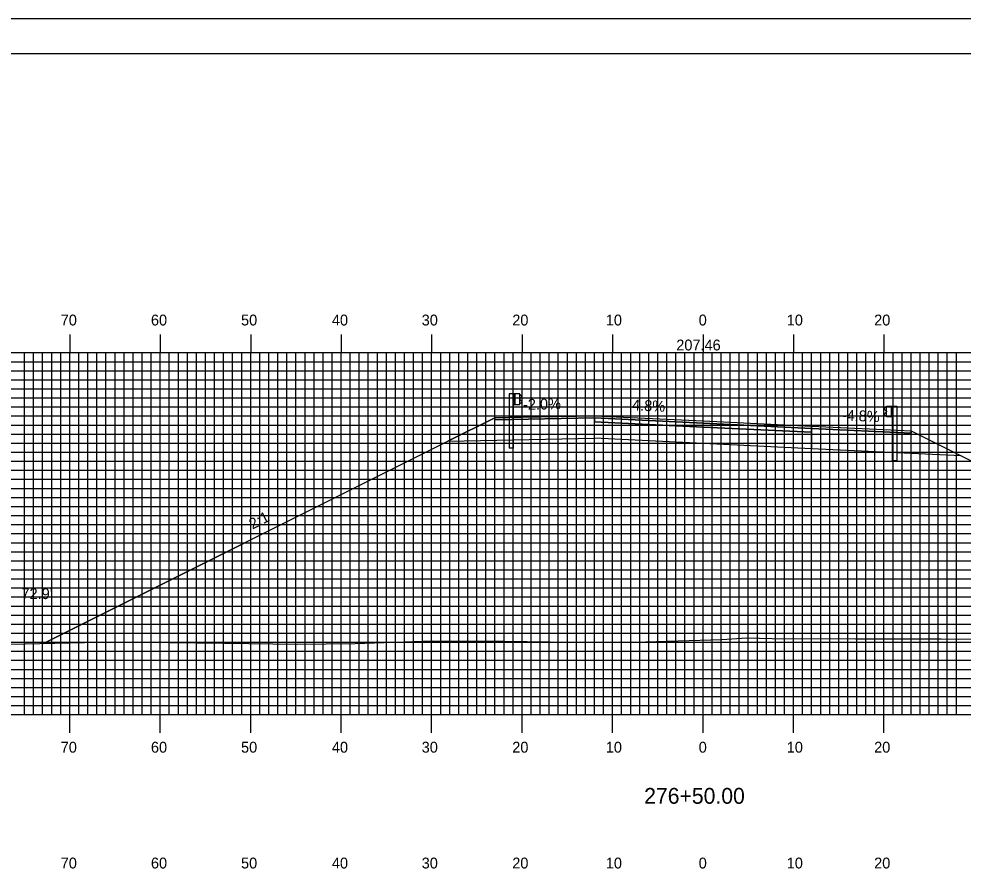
# Model space of a CAD drawing. Extents: x 1809800 to 1810143, y 442591 to 442811.
# Drawn here: x 1809889.7 to 1809994.1, y 442716.2 to 442810.5 of the extents above; entities that cross this region are included whole.
import ezdxf

# ---------------------------------------------------------------- set-up
doc = ezdxf.new("R2010")
doc.units = 0
for name, color, linetype in [('ANNOTATION', 7, 'Continuous'), ('BORDER', 7, 'Continuous'), ('D_Guardrail_Beam_Lt', 7, 'Continuous'), ('D_Guardrail_Beam_Rt', 7, 'Continuous'), ('D_Roadway_Centerline', 7, 'Continuous'), ('D_Roadway_Centerline_Text', 7, 'Continuous'), ('D_Roadway_Edge_Shoulder', 7, 'Continuous'), ('D_Roadway_Edge_TW', 7, 'Continuous'), ('D_Roadway_Pavement', 7, 'Continuous'), ('D_Roadway_SlopeLines', 7, 'Continuous'), ('D_Roadway_SubGrade', 7, 'Continuous'), ('D_Text_Standard', 7, 'Continuous'), ('H_V ANNOTATION', 7, 'Continuous'), ('MAJOR', 7, 'Continuous'), ('MINOR', 7, 'Continuous'), ('PLOT BOUNDARY', 7, 'Continuous'), ('S_Roadway_Centerline', 7, 'Continuous')]:
    doc.layers.add(name, color=color, linetype=linetype)

msp = doc.modelspace()

# ---------------------------------------------------------------- linework, layer by layer
at = {"layer": 'BORDER'}
msp.add_lwpolyline([(1809815.75, 442596.67), (1810135.75, 442596.67), (1810135.75, 442806.67), (1809815.75, 442806.67)], close=True, dxfattribs=at)
at = {"layer": 'D_Guardrail_Beam_Lt'}
for p, q in [((1809943.92, 442769.12), (1809943.92, 442763.12)), ((1809944.39, 442769.12), (1809943.92, 442769.12)), ((1809945.08, 442769.12), (1809944.39, 442769.12)), ((1809944.39, 442769.12), (1809944.39, 442767.95)), ((1809944.45, 442769.12), (1809944.45, 442767.95)), ((1809944.56, 442769.12), (1809944.56, 442767.95)), ((1809945.08, 442767.95), (1809945.08, 442769.12)), ((1809945.08, 442769.04), (1809945.15, 442769.02)), ((1809945.31, 442768.77), (1809945.12, 442768.64)), ((1809945.17, 442769.01), (1809945.31, 442768.91)), ((1809944.39, 442767.95), (1809945.08, 442767.95)), ((1809944.41, 442763.12), (1809944.41, 442767.95)), ((1809945.08, 442768.57), (1809945.08, 442768.5)), ((1809945.15, 442768.05), (1809945.08, 442768.04)), ((1809945.12, 442768.44), (1809945.31, 442768.3)), ((1809945.31, 442768.16), (1809945.17, 442768.06)), ((1809944.41, 442763.12), (1809943.92, 442763.12))]:
    msp.add_line(p, q, dxfattribs=at)
for centre, major_axis, start_param, end_param in [((1809945.16, 442768.57), (-0.0789, 0), 5.323254, 6.283185), ((1809945.15, 442768.98), (0.0417, 0), 0.959931, 1.376053), ((1809945.26, 442768.84), (0.0877, 0), 5.323254, 7.243116), ((1809945.16, 442768.5), (-0.0789, 0), 6.283185, 7.243116), ((1809945.15, 442768.09), (0.0417, 0), 4.907132, 5.323254), ((1809945.26, 442768.23), (0.0877, 0), 5.323254, 7.243116)]:
    msp.add_ellipse(centre, major_axis=major_axis, ratio=0.995501, start_param=start_param, end_param=end_param, dxfattribs=at)
at = {"layer": 'D_Guardrail_Beam_Rt'}
for p, q in [((1809985.53, 442767.64), (1809985.39, 442767.54)), ((1809985.62, 442767.66), (1809985.55, 442767.65)), ((1809985.62, 442767.74), (1809986.31, 442767.74)), ((1809985.62, 442766.58), (1809985.62, 442767.74)), ((1809986.14, 442767.74), (1809986.14, 442766.58)), ((1809986.25, 442767.74), (1809986.25, 442766.58)), ((1809986.31, 442767.74), (1809986.78, 442767.74)), ((1809986.31, 442767.74), (1809986.31, 442766.58)), ((1809986.78, 442767.74), (1809986.78, 442761.74)), ((1809985.39, 442767.4), (1809985.58, 442767.26)), ((1809985.58, 442767.06), (1809985.39, 442766.92)), ((1809985.39, 442766.78), (1809985.53, 442766.68)), ((1809985.55, 442766.67), (1809985.62, 442766.66)), ((1809985.62, 442767.2), (1809985.62, 442767.13)), ((1809986.31, 442766.58), (1809985.62, 442766.58)), ((1809986.29, 442761.74), (1809986.29, 442766.58)), ((1809986.29, 442761.74), (1809986.78, 442761.74))]:
    msp.add_line(p, q, dxfattribs=at)
for centre, major_axis, start_param, end_param in [((1809985.56, 442767.6), (-0.0417, 0), 4.907132, 5.323254), ((1809985.44, 442767.47), (-0.0877, 0), 5.323254, 7.243116), ((1809985.44, 442766.85), (-0.0877, 0), 5.323254, 7.243116), ((1809985.56, 442766.72), (-0.0417, 0), 0.959931, 1.376053), ((1809985.54, 442767.2), (0.0789, 0), 0, 0.959931), ((1809985.54, 442767.13), (0.0789, 0), 5.323254, 6.283185)]:
    msp.add_ellipse(centre, major_axis=major_axis, ratio=0.995501, start_param=start_param, end_param=end_param, dxfattribs=at)
at = {"layer": 'D_Roadway_Centerline'}
msp.add_lwpolyline([(1809892.44, 442741.52), (1809937.14, 442763.87), (1809942.35, 442766.48), (1809945.35, 442766.54), (1809953.35, 442766.7), (1809965.35, 442766.12), (1809977.35, 442765.54), (1809985.35, 442765.16), (1809988.35, 442765.02), (1809993.88, 442762.25), (1810034.75, 442741.82)], dxfattribs=at)
at = {"layer": 'D_Roadway_Edge_Shoulder'}
for points in [[(1809953.35, 442766.7), (1809945.35, 442766.54), (1809945.35, 442766.54), (1809942.35, 442766.48), (1809942.35, 442766.23), (1809953.35, 442766.45)], [(1809977.35, 442765.54), (1809985.35, 442765.16), (1809985.35, 442765.16), (1809988.35, 442765.02), (1809988.35, 442764.77), (1809977.35, 442765.29)]]:
    msp.add_lwpolyline(points, close=True, dxfattribs=at)
at = {"layer": 'D_Roadway_Edge_TW'}
msp.add_lwpolyline([(1809953.35, 442766.45), (1809953.35, 442766.7), (1809965.35, 442766.12), (1809977.35, 442765.54), (1809977.35, 442765.29), (1809965.35, 442765.87)], close=True, dxfattribs=at)
at = {"layer": 'D_Roadway_Pavement'}
msp.add_lwpolyline([(1809953.35, 442766.03), (1809953.35, 442766.45), (1809965.35, 442765.87), (1809977.35, 442765.29), (1809977.35, 442764.88), (1809965.35, 442765.45)], close=True, dxfattribs=at)
for points in [[(1809953.35, 442766.45), (1809953.35, 442766.03)], [(1809977.35, 442765.29), (1809977.35, 442764.88)]]:
    msp.add_lwpolyline(points, dxfattribs=at)
at = {"layer": 'D_Roadway_SlopeLines'}
for points in [[(1809942.35, 442766.48), (1809892.44, 442741.52)], [(1809988.35, 442765.02), (1810034.75, 442741.82)]]:
    msp.add_lwpolyline(points, dxfattribs=at)
at = {"layer": 'D_Roadway_SubGrade'}
for points in [[(1809953.35, 442766.03), (1809953.35, 442766.45), (1809942.35, 442766.23), (1809942.35, 442766.48), (1809937.14, 442763.87), (1809953.35, 442764.2)], [(1809953.35, 442764.2), (1809953.35, 442766.45), (1809953.35, 442766.03), (1809965.35, 442765.45), (1809977.35, 442764.88), (1809977.35, 442765.29), (1809977.35, 442763.04), (1809965.35, 442763.62)], [(1809977.35, 442764.88), (1809977.35, 442765.29), (1809988.35, 442764.77), (1809988.35, 442765.02), (1809993.88, 442762.25), (1809977.35, 442763.04)]]:
    msp.add_lwpolyline(points, close=True, dxfattribs=at)
at = {"layer": 'MAJOR'}
for p, q in [((1809895.35, 442775.67), (1809895.35, 442773.67)), ((1809905.35, 442775.67), (1809905.35, 442773.67)), ((1809915.35, 442775.67), (1809915.35, 442773.67)), ((1809925.35, 442775.67), (1809925.35, 442773.67)), ((1809935.35, 442775.67), (1809935.35, 442773.67)), ((1809945.35, 442775.67), (1809945.35, 442773.67)), ((1809955.35, 442775.67), (1809955.35, 442773.67)), ((1809965.35, 442775.67), (1809965.35, 442773.67)), ((1809975.35, 442775.67), (1809975.35, 442773.67)), ((1809985.35, 442775.67), (1809985.35, 442773.67)), ((1809825.35, 442773.67), (1810105.35, 442773.67)), ((1809825.35, 442773.67), (1810105.35, 442773.67)), ((1809895.35, 442733.67), (1809895.35, 442773.67)), ((1809905.35, 442733.67), (1809905.35, 442773.67)), ((1809915.35, 442733.67), (1809915.35, 442773.67)), ((1809925.35, 442733.67), (1809925.35, 442773.67)), ((1809935.35, 442733.67), (1809935.35, 442773.67)), ((1809945.35, 442733.67), (1809945.35, 442773.67)), ((1809955.35, 442733.67), (1809955.35, 442773.67)), ((1809965.35, 442733.67), (1809965.35, 442773.67)), ((1809975.35, 442733.67), (1809975.35, 442773.67)), ((1809985.35, 442733.67), (1809985.35, 442773.67)), ((1809825.35, 442768.67), (1810105.35, 442768.67)), ((1809825.35, 442763.67), (1810105.35, 442763.67)), ((1809825.35, 442758.67), (1810105.35, 442758.67)), ((1809825.35, 442753.67), (1810105.35, 442753.67)), ((1809825.35, 442748.67), (1810105.35, 442748.67)), ((1809825.35, 442743.67), (1810105.35, 442743.67)), ((1809825.35, 442738.67), (1810105.35, 442738.67)), ((1809825.35, 442733.67), (1810105.35, 442733.67)), ((1809825.35, 442733.67), (1810105.35, 442733.67)), ((1809895.35, 442731.66), (1809895.35, 442733.67)), ((1809905.35, 442731.66), (1809905.35, 442733.67)), ((1809915.35, 442731.66), (1809915.35, 442733.67)), ((1809925.35, 442731.66), (1809925.35, 442733.67)), ((1809935.35, 442731.66), (1809935.35, 442733.67)), ((1809945.35, 442731.66), (1809945.35, 442733.67)), ((1809955.35, 442731.66), (1809955.35, 442733.67)), ((1809965.35, 442731.66), (1809965.35, 442733.67)), ((1809975.35, 442731.66), (1809975.35, 442733.67)), ((1809985.35, 442731.66), (1809985.35, 442733.67))]:
    msp.add_line(p, q, dxfattribs=at)
at = {"layer": 'MINOR'}
for p, q in [((1809890.35, 442733.67), (1809890.35, 442773.67)), ((1809891.35, 442733.67), (1809891.35, 442773.67)), ((1809892.35, 442733.67), (1809892.35, 442773.67)), ((1809893.35, 442733.67), (1809893.35, 442773.67)), ((1809894.35, 442733.67), (1809894.35, 442773.67)), ((1809896.35, 442733.67), (1809896.35, 442773.67)), ((1809897.35, 442733.67), (1809897.35, 442773.67)), ((1809898.35, 442733.67), (1809898.35, 442773.67)), ((1809899.35, 442733.67), (1809899.35, 442773.67)), ((1809900.35, 442733.67), (1809900.35, 442773.67)), ((1809901.35, 442733.67), (1809901.35, 442773.67)), ((1809902.35, 442733.67), (1809902.35, 442773.67)), ((1809903.35, 442733.67), (1809903.35, 442773.67)), ((1809904.35, 442733.67), (1809904.35, 442773.67)), ((1809906.35, 442733.67), (1809906.35, 442773.67)), ((1809907.35, 442733.67), (1809907.35, 442773.67)), ((1809908.35, 442733.67), (1809908.35, 442773.67)), ((1809909.35, 442733.67), (1809909.35, 442773.67)), ((1809910.35, 442733.67), (1809910.35, 442773.67)), ((1809911.35, 442733.67), (1809911.35, 442773.67)), ((1809912.35, 442733.67), (1809912.35, 442773.67)), ((1809913.35, 442733.67), (1809913.35, 442773.67)), ((1809914.35, 442733.67), (1809914.35, 442773.67)), ((1809916.35, 442733.67), (1809916.35, 442773.67)), ((1809917.35, 442733.67), (1809917.35, 442773.67)), ((1809918.35, 442733.67), (1809918.35, 442773.67)), ((1809919.35, 442733.67), (1809919.35, 442773.67)), ((1809920.35, 442733.67), (1809920.35, 442773.67)), ((1809921.35, 442733.67), (1809921.35, 442773.67)), ((1809922.35, 442733.67), (1809922.35, 442773.67)), ((1809923.35, 442733.67), (1809923.35, 442773.67)), ((1809924.35, 442733.67), (1809924.35, 442773.67)), ((1809926.35, 442733.67), (1809926.35, 442773.67)), ((1809927.35, 442733.67), (1809927.35, 442773.67)), ((1809928.35, 442733.67), (1809928.35, 442773.67)), ((1809929.35, 442733.67), (1809929.35, 442773.67)), ((1809930.35, 442733.67), (1809930.35, 442773.67)), ((1809931.35, 442733.67), (1809931.35, 442773.67)), ((1809932.35, 442733.67), (1809932.35, 442773.67)), ((1809933.35, 442733.67), (1809933.35, 442773.67)), ((1809934.35, 442733.67), (1809934.35, 442773.67)), ((1809936.35, 442733.67), (1809936.35, 442773.67)), ((1809937.35, 442733.67), (1809937.35, 442773.67)), ((1809938.35, 442733.67), (1809938.35, 442773.67)), ((1809939.35, 442733.67), (1809939.35, 442773.67)), ((1809940.35, 442733.67), (1809940.35, 442773.67)), ((1809941.35, 442733.67), (1809941.35, 442773.67)), ((1809942.35, 442733.67), (1809942.35, 442773.67)), ((1809943.35, 442733.67), (1809943.35, 442773.67)), ((1809944.35, 442733.67), (1809944.35, 442773.67)), ((1809946.35, 442733.67), (1809946.35, 442773.67)), ((1809947.35, 442733.67), (1809947.35, 442773.67)), ((1809948.35, 442733.67), (1809948.35, 442773.67)), ((1809949.35, 442733.67), (1809949.35, 442773.67)), ((1809950.35, 442733.67), (1809950.35, 442773.67)), ((1809951.35, 442733.67), (1809951.35, 442773.67)), ((1809952.35, 442733.67), (1809952.35, 442773.67)), ((1809953.35, 442733.67), (1809953.35, 442773.67)), ((1809954.35, 442733.67), (1809954.35, 442773.67)), ((1809956.35, 442733.67), (1809956.35, 442773.67)), ((1809957.35, 442733.67), (1809957.35, 442773.67)), ((1809958.35, 442733.67), (1809958.35, 442773.67)), ((1809959.35, 442733.67), (1809959.35, 442773.67)), ((1809960.35, 442733.67), (1809960.35, 442773.67)), ((1809961.35, 442733.67), (1809961.35, 442773.67)), ((1809962.35, 442733.67), (1809962.35, 442773.67)), ((1809963.35, 442733.67), (1809963.35, 442773.67)), ((1809964.35, 442733.67), (1809964.35, 442773.67)), ((1809966.35, 442733.67), (1809966.35, 442773.67)), ((1809967.35, 442733.67), (1809967.35, 442773.67)), ((1809968.35, 442733.67), (1809968.35, 442773.67)), ((1809969.35, 442733.67), (1809969.35, 442773.67)), ((1809970.35, 442733.67), (1809970.35, 442773.67)), ((1809971.35, 442733.67), (1809971.35, 442773.67)), ((1809972.35, 442733.67), (1809972.35, 442773.67)), ((1809973.35, 442733.67), (1809973.35, 442773.67)), ((1809974.35, 442733.67), (1809974.35, 442773.67)), ((1809976.35, 442733.67), (1809976.35, 442773.67)), ((1809977.35, 442733.67), (1809977.35, 442773.67)), ((1809978.35, 442733.67), (1809978.35, 442773.67)), ((1809979.35, 442733.67), (1809979.35, 442773.67)), ((1809980.35, 442733.67), (1809980.35, 442773.67)), ((1809981.35, 442733.67), (1809981.35, 442773.67)), ((1809982.35, 442733.67), (1809982.35, 442773.67)), ((1809983.35, 442733.67), (1809983.35, 442773.67)), ((1809984.35, 442733.67), (1809984.35, 442773.67)), ((1809986.35, 442733.67), (1809986.35, 442773.67)), ((1809987.35, 442733.67), (1809987.35, 442773.67)), ((1809988.35, 442733.67), (1809988.35, 442773.67)), ((1809989.35, 442733.67), (1809989.35, 442773.67)), ((1809990.35, 442733.67), (1809990.35, 442773.67)), ((1809991.35, 442733.67), (1809991.35, 442773.67)), ((1809992.35, 442733.67), (1809992.35, 442773.67)), ((1809993.35, 442733.67), (1809993.35, 442773.67)), ((1809825.35, 442772.67), (1810105.35, 442772.67)), ((1809825.35, 442771.67), (1810105.35, 442771.67)), ((1809825.35, 442770.67), (1810105.35, 442770.67)), ((1809825.35, 442769.67), (1810105.35, 442769.67)), ((1809825.35, 442767.67), (1810105.35, 442767.67)), ((1809825.35, 442766.67), (1810105.35, 442766.67)), ((1809825.35, 442765.67), (1810105.35, 442765.67)), ((1809825.35, 442764.67), (1810105.35, 442764.67)), ((1809825.35, 442762.67), (1810105.35, 442762.67)), ((1809825.35, 442761.67), (1810105.35, 442761.67)), ((1809825.35, 442760.67), (1810105.35, 442760.67)), ((1809825.35, 442759.67), (1810105.35, 442759.67)), ((1809825.35, 442757.67), (1810105.35, 442757.67)), ((1809825.35, 442756.67), (1810105.35, 442756.67)), ((1809825.35, 442755.67), (1810105.35, 442755.67)), ((1809825.35, 442754.67), (1810105.35, 442754.67)), ((1809825.35, 442752.67), (1810105.35, 442752.67)), ((1809825.35, 442751.67), (1810105.35, 442751.67)), ((1809825.35, 442750.67), (1810105.35, 442750.67)), ((1809825.35, 442749.67), (1810105.35, 442749.67)), ((1809825.35, 442747.67), (1810105.35, 442747.67)), ((1809825.35, 442746.67), (1810105.35, 442746.67)), ((1809825.35, 442745.67), (1810105.35, 442745.67)), ((1809825.35, 442744.67), (1810105.35, 442744.67)), ((1809825.35, 442742.67), (1810105.35, 442742.67)), ((1809825.35, 442741.67), (1810105.35, 442741.67)), ((1809825.35, 442740.67), (1810105.35, 442740.67)), ((1809825.35, 442739.67), (1810105.35, 442739.67)), ((1809825.35, 442737.67), (1810105.35, 442737.67)), ((1809825.35, 442736.67), (1810105.35, 442736.67)), ((1809825.35, 442735.67), (1810105.35, 442735.67)), ((1809825.35, 442734.67), (1810105.35, 442734.67))]:
    msp.add_line(p, q, dxfattribs=at)
at = {"layer": 'PLOT BOUNDARY'}
msp.add_lwpolyline([(1809799.56, 442590.55), (1810139.56, 442590.55), (1810139.56, 442810.55), (1809799.56, 442810.55)], close=True, dxfattribs=at)
at = {"layer": 'S_Roadway_Centerline'}
msp.add_lwpolyline([(1809877.29, 442741.19), (1809898.61, 442741.66), (1809900.89, 442741.66), (1809903.26, 442741.66), (1809912.44, 442741.58), (1809920.49, 442741.46), (1809926.9, 442741.53), (1809935.49, 442741.81), (1809943.39, 442741.79), (1809948.45, 442741.73), (1809957.76, 442741.67), (1809967.42, 442741.98), (1809970.2, 442742.14), (1809972.99, 442742.09), (1809982.19, 442742.06), (1809991.67, 442742.04), (1809993.6, 442742), (1809995.7, 442742.05)], dxfattribs=at)

# ---------------------------------------------------------------- texts
at = {"layer": 'ANNOTATION'}
for s, rotation, p in [('-2.0%', 1.1458, (1809945.46, 442767.34)), ('4.8%', 357.2519, (1809957.48, 442767.3)), ('-4.8%', 357.2519, (1809980.66, 442766.19)), ('2:1', 26.5651, (1809915.54, 442754.11))]:
    msp.add_text(s, height=1.2, rotation=rotation, dxfattribs=at).set_placement(p)
at = {"layer": 'D_Roadway_Centerline'}
for s, p in [('C', (1809965.35, 442766.12)), ('L', (1809965.35, 442766.11))]:
    msp.add_text(s, height=0.0146, dxfattribs=at).set_placement(p)
at = {"layer": 'D_Roadway_Centerline_Text'}
msp.add_text('207.46', height=1.2, dxfattribs=at).set_placement((1809962.39, 442773.91))
at = {"layer": 'D_Text_Standard'}
msp.add_text("72.9'", height=1.2, dxfattribs=at).set_placement((1809890.01, 442746.44))
at = {"layer": 'H_V ANNOTATION'}
for s, height, p in [('70', 1.2, (1809894.35, 442776.67)), ('60', 1.2, (1809904.32, 442776.67)), ('50', 1.2, (1809914.28, 442776.67)), ('40', 1.2, (1809924.32, 442776.67)), ('30', 1.2, (1809934.25, 442776.67)), ('20', 1.2, (1809944.26, 442776.67)), ('10', 1.2, (1809954.6, 442776.67)), ('0', 1.2, (1809964.87, 442776.67)), ('10', 1.2, (1809974.6, 442776.67)), ('20', 1.2, (1809984.26, 442776.67)), ('70', 1.2, (1809894.35, 442729.47)), ('60', 1.2, (1809904.32, 442729.47)), ('50', 1.2, (1809914.28, 442729.47)), ('40', 1.2, (1809924.32, 442729.47)), ('30', 1.2, (1809934.25, 442729.47)), ('20', 1.2, (1809944.26, 442729.47)), ('10', 1.2, (1809954.6, 442729.47)), ('0', 1.2, (1809964.87, 442729.47)), ('10', 1.2, (1809974.6, 442729.47)), ('20', 1.2, (1809984.26, 442729.47)), ('276+50.00', 1.75, (1809958.84, 442723.82)), ('70', 1.2, (1809894.35, 442716.67)), ('60', 1.2, (1809904.32, 442716.67)), ('50', 1.2, (1809914.28, 442716.67)), ('40', 1.2, (1809924.32, 442716.67)), ('30', 1.2, (1809934.25, 442716.67)), ('20', 1.2, (1809944.26, 442716.67)), ('10', 1.2, (1809954.6, 442716.67)), ('0', 1.2, (1809964.87, 442716.67)), ('10', 1.2, (1809974.6, 442716.67)), ('20', 1.2, (1809984.26, 442716.67))]:
    msp.add_text(s, height=height, dxfattribs=at).set_placement(p)

doc.saveas('drawing.dxf')
